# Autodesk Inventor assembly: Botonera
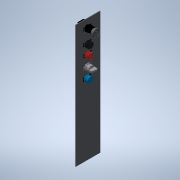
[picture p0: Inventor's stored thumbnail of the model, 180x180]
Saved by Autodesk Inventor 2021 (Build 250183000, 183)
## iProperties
Created: 2021-02
Part Number: Botonera
Material: Genérico
Document SubType Name: Assembly
Designer: ATOUZA
Author: ATOUZA
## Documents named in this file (5)
- D:\01 Paralaia\Grupos de Traballo\GT Maquetas\CAD 3D\E_Alimentación\Botonera.iam
- D:\01 Paralaia\Grupos de Traballo\GT Maquetas\CAD 3D\E_Alimentación\Placa botonera.ipt
- D:\01 Paralaia\Grupos de Traballo\GT Maquetas\CAD 3D\E_Alimentación\Pulsador XB5AA21\xb5_aa21.iam
- D:\01 Paralaia\Grupos de Traballo\GT Maquetas\CAD 3D\E_Alimentación\Selector XB5AD33\xb5_ad33.iam
- D:\01 Paralaia\Grupos de Traballo\GT Maquetas\CAD 3D\E_Alimentación\Seta XB5AS8445\xb5_as8445.iam
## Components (6 placed, 4 different names)
1. Placa botonera:1 — Coincidencia:1, Coincidencia:2, Coincidencia:3, Coincidencia:4, Coincidencia:5
2. xb5_aa21:1 [sub-assembly] — Coincidencia:1
3. xb5_aa21:2 [sub-assembly] — Coincidencia:2
4. xb5_aa21:3 [sub-assembly] — Coincidencia:3
5. xb5_ad33:1 [sub-assembly] — Coincidencia:4
6. xb5_as8445:1 [sub-assembly] — Coincidencia:5
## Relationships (5: Mate 5)
- Coincidencia:1 [Mate]: Placa botonera:1 ↔ xb5_aa21:1
- Coincidencia:2 [Mate]: Placa botonera:1 ↔ xb5_aa21:2
- Coincidencia:3 [Mate]: Placa botonera:1 ↔ xb5_aa21:3
- Coincidencia:4 [Mate]: Placa botonera:1 ↔ xb5_ad33:1
- Coincidencia:5 [Mate]: Placa botonera:1 ↔ xb5_as8445:1
